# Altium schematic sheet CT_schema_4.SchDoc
size 294 x 169 mm
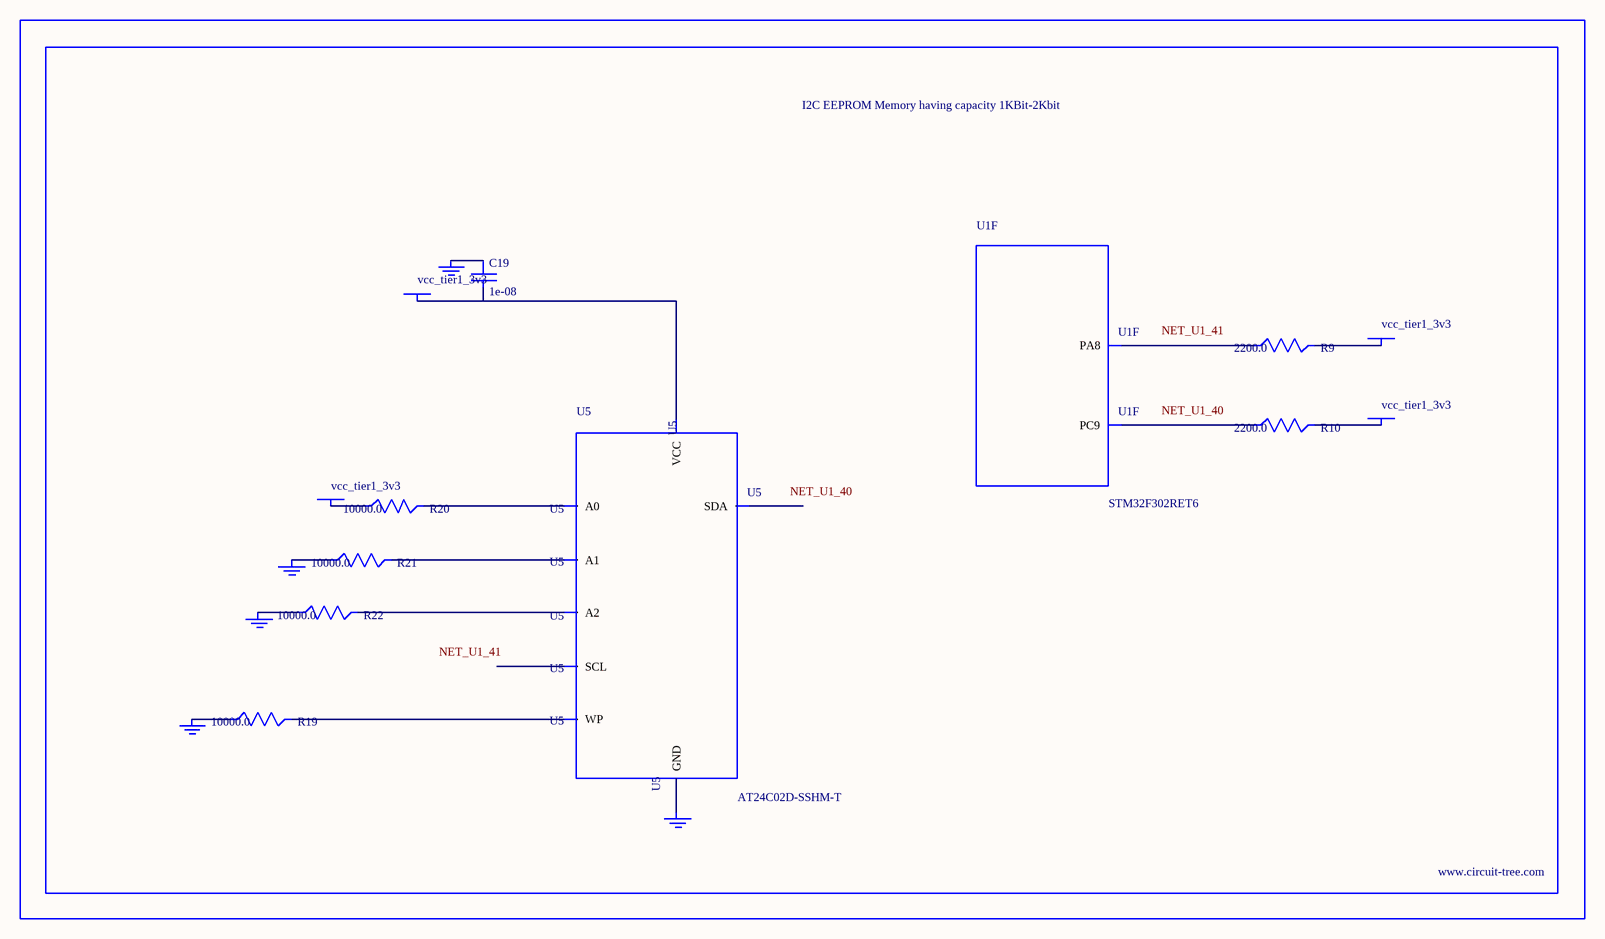
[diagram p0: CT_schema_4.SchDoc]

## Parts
BORDER3  (no value)
C19  1e-08  [C0402]
GND_INSTANCE_3_0  (no value)
GND_INSTANCE_3_1  (no value)
GND_INSTANCE_3_2  (no value)
GND_INSTANCE_3_3  (no value)
GND_INSTANCE_3_4  (no value)
POWER_INSTANCE_3_0  vcc_tier1_3v3
POWER_INSTANCE_3_1  vcc_tier1_3v3
POWER_INSTANCE_3_2  vcc_tier1_3v3
POWER_INSTANCE_3_3  vcc_tier1_3v3
R9  2200.0  [R0603]
R10  2200.0  [R0603]
R19  10000.0  [R0603]
R20  10000.0  [R0603]
R21  10000.0  [R0603]
R22  10000.0  [R0603]
U1  STM32F302RET6  [LQFP64]  (part F of 7)
U5  AT24C02D-SSHM-T  [AT24C02D]

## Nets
NetC19_1: C19.1 GND_INSTANCE_3_3.0(GND)
NetC19_2: C19.2 POWER_INSTANCE_3_1.0(PWR) U5.8(VCC)
NetGND_INSTANCE_3_0_0: GND_INSTANCE_3_0.0(GND) R21.1
NetGND_INSTANCE_3_1_0: GND_INSTANCE_3_1.0(GND) R22.1
NetGND_INSTANCE_3_2_0: GND_INSTANCE_3_2.0(GND) R19.1
NetGND_INSTANCE_3_4_0: GND_INSTANCE_3_4.0(GND) U5.4(GND)
NetPOWER_INSTANCE_3_0_0: POWER_INSTANCE_3_0.0(PWR) R20.1
NetPOWER_INSTANCE_3_2_0: POWER_INSTANCE_3_2.0(PWR) R10.2
NetPOWER_INSTANCE_3_3_0: POWER_INSTANCE_3_3.0(PWR) R9.2
NetR9_1: R9.1 U1.41(PA8)
NetR10_1: R10.1 U1.40(PC9)
NetR19_2: R19.2 U5.7(WP)
NetR20_2: R20.2 U5.1(A0)
NetR21_2: R21.2 U5.2(A1)
NetR22_2: R22.2 U5.3(A2)

Not connected (* = marked no-connect by the designer): U5 5(SDA) 6(SCL)

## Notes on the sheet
- Labels drawn without touching a wire or pin: NET_U1_40, NET_U1_41

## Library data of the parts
BORDER3 = BORDER_PAGE3
C19 = C0402C103K3RAC
GND_INSTANCE_3_0-GND_INSTANCE_3_4 = GND
POWER_INSTANCE_3_0-POWER_INSTANCE_3_3 = PWR
R9 R10 = RC0603JR-072K2L
R19-R22 = RC0603JR-0710KL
